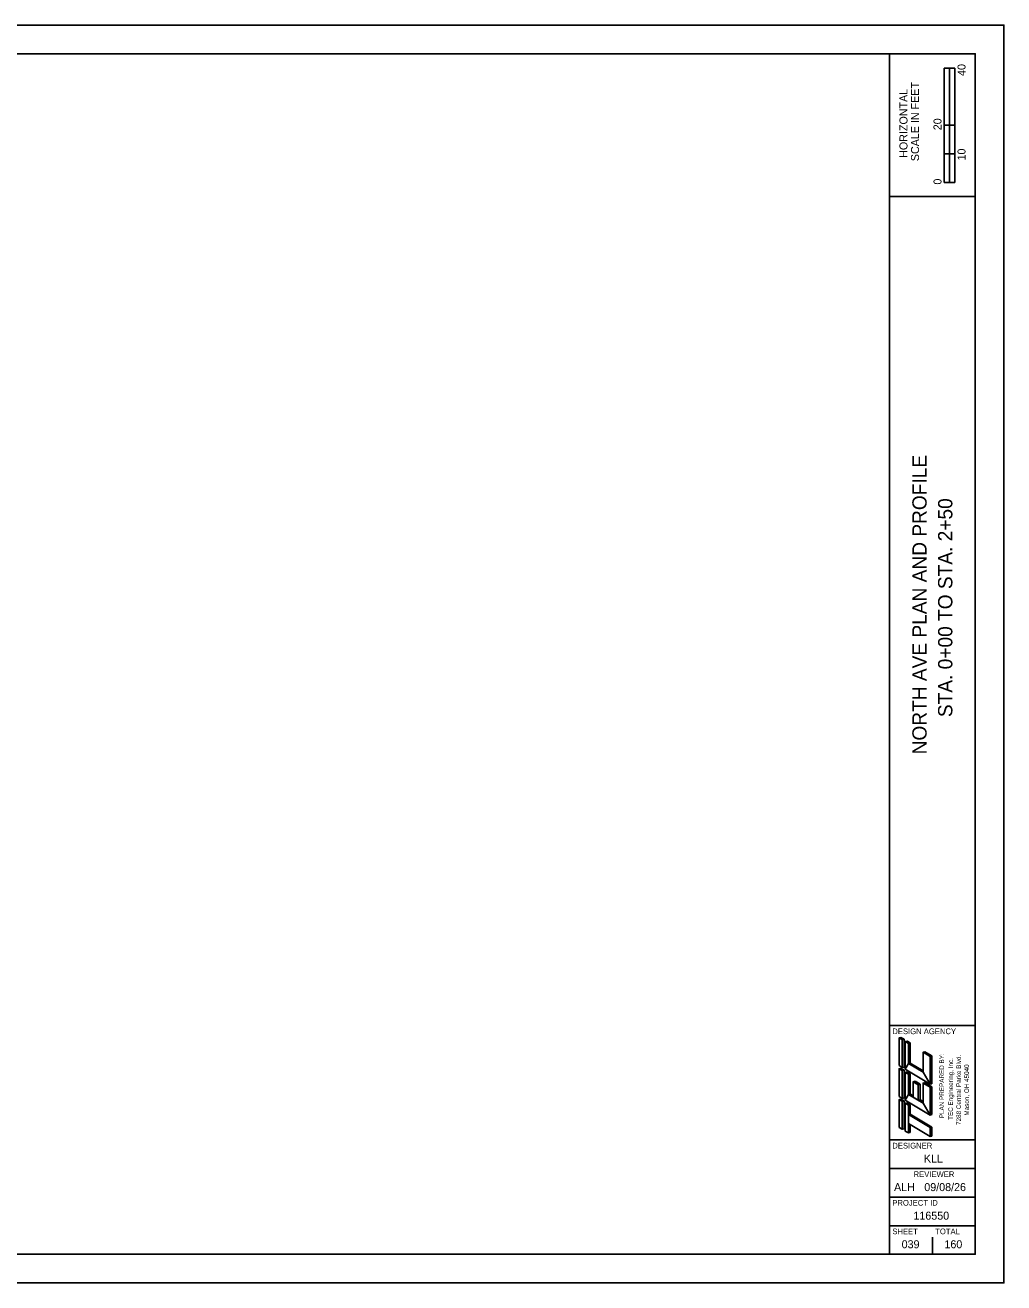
# Model space of a CAD drawing. Extents: x -0.2 to 34, y 0 to 22.
# Drawn here: x 16.89 to 34, y 0 to 22 of the extents above; entities that cross this region are included whole.
import ezdxf

# ---------------------------------------------------------------- set-up
doc = ezdxf.new("R2010")
doc.units = 0
for name, color, linetype in [('Default', 7, 'Continuous'), ('DT_X_Contour_Major', 7, 'Continuous'), ('DT_X_Contour_Minor', 7, 'Continuous'), ('DT_X_Spot_Elev', 7, 'Continuous'), ('DT_X_Void', 7, 'Continuous')]:
    doc.layers.add(name, color=color, linetype=linetype)

msp = doc.modelspace()

# ---------------------------------------------------------------- linework, layer by layer
at = {"layer": 'DT_X_Contour_Major'}
for p, q in [((32, 0.5), (32, 21.5)), ((32, 19), (33.5, 19)), ((32, 4.5), (33.5, 4.5)), ((32, 2.5), (33.5, 2.5)), ((32, 2), (33.5, 2)), ((32, 1.5), (33.5, 1.5)), ((32, 1), (33.5, 1))]:
    msp.add_line(p, q, dxfattribs=at)
msp.add_lwpolyline([(1.5, 21.5), (33.5, 21.5), (33.5, 0.5), (1.5, 0.5)], close=True, dxfattribs=at)
at = {"layer": 'DT_X_Contour_Minor'}
msp.add_lwpolyline([(0, 0), (34, 0), (34, 22), (0, 22)], close=True, dxfattribs=at)
at = {"layer": 'DT_X_Spot_Elev'}
for p, q in [((32.957, 19.25), (32.957, 21.25)), ((33.144, 21.25), (32.957, 21.25)), ((32.957, 20.25), (32.957, 21.25)), ((32.957, 21.25), (33.05, 21.25)), ((33.05, 21.25), (33.051, 21.25)), ((33.051, 21.25), (33.051, 20.25)), ((33.144, 21.25), (33.144, 19.25)), ((33.051, 20.25), (32.957, 20.25)), ((33.143, 20.25), (33.05, 20.25)), ((33.05, 20.25), (33.05, 19.75)), ((33.143, 19.75), (33.143, 20.25)), ((33.05, 19.75), (32.957, 19.75)), ((32.957, 19.75), (32.957, 19.25)), ((33.05, 19.25), (33.05, 19.75)), ((33.05, 19.75), (33.143, 19.75)), ((33.144, 19.25), (32.957, 19.25)), ((32.957, 19.25), (33.05, 19.25)), ((32.75, 3.5), (32.75, 3.5)), ((32.375, 0.675), (32.375, 0.675)), ((32.75, 0.5), (32.75, 0.8))]:
    msp.add_line(p, q, dxfattribs=at)
at = {"layer": 'DT_X_Void'}
for p, q in [((32.169, 4.285), (32.201, 4.294)), ((32.169, 3.799), (32.169, 4.285)), ((32.223, 4.253), (32.169, 4.285)), ((32.255, 4.261), (32.201, 4.294)), ((32.223, 4.253), (32.255, 4.261)), ((32.223, 3.767), (32.223, 4.253)), ((32.255, 3.775), (32.255, 4.261)), ((32.277, 4.221), (32.309, 4.229)), ((32.331, 4.188), (32.277, 4.221)), ((32.277, 3.735), (32.277, 4.221)), ((32.309, 4.229), (32.363, 4.196)), ((32.331, 4.188), (32.363, 4.196)), ((32.331, 3.837), (32.331, 4.188)), ((32.363, 4.196), (32.363, 3.845)), ((32.587, 4.034), (32.62, 4.042)), ((32.587, 3.683), (32.587, 4.034)), ((32.709, 3.961), (32.587, 4.034)), ((32.62, 4.042), (32.741, 3.97)), ((32.709, 3.961), (32.741, 3.97)), ((32.709, 3.475), (32.709, 3.961)), ((32.741, 3.97), (32.741, 3.484)), ((32.223, 3.767), (32.169, 3.799)), ((32.169, 3.745), (32.201, 3.754)), ((32.169, 3.259), (32.169, 3.745)), ((32.223, 3.713), (32.169, 3.745)), ((32.255, 3.722), (32.201, 3.754)), ((32.223, 3.767), (32.255, 3.775)), ((32.331, 3.837), (32.363, 3.845)), ((32.587, 3.683), (32.331, 3.837)), ((32.363, 3.845), (32.587, 3.711)), ((32.223, 3.713), (32.255, 3.722)), ((32.223, 3.227), (32.223, 3.713)), ((32.255, 3.236), (32.255, 3.722)), ((32.709, 3.475), (32.277, 3.735)), ((32.277, 3.681), (32.309, 3.689)), ((32.277, 3.195), (32.277, 3.681)), ((32.331, 3.648), (32.277, 3.681)), ((32.309, 3.689), (32.363, 3.656)), ((32.331, 3.648), (32.363, 3.656)), ((32.331, 3.297), (32.331, 3.648)), ((32.363, 3.656), (32.363, 3.305)), ((32.415, 3.519), (32.448, 3.527)), ((32.448, 3.527), (32.535, 3.474)), ((32.331, 3.297), (32.363, 3.305)), ((32.363, 3.305), (32.415, 3.274)), ((32.415, 3.519), (32.415, 3.247)), ((32.415, 3.519), (32.503, 3.466)), ((32.503, 3.466), (32.535, 3.474)), ((32.503, 3.466), (32.503, 3.194)), ((32.535, 3.474), (32.535, 3.202)), ((32.587, 3.494), (32.62, 3.502)), ((32.587, 3.143), (32.587, 3.494)), ((32.709, 3.421), (32.587, 3.494)), ((32.62, 3.502), (32.741, 3.43)), ((32.709, 3.475), (32.741, 3.484)), ((32.709, 3.421), (32.741, 3.43)), ((32.709, 2.935), (32.709, 3.421)), ((32.741, 3.43), (32.741, 2.944)), ((32.223, 3.227), (32.169, 3.259)), ((32.169, 3.205), (32.201, 3.215)), ((32.169, 2.719), (32.169, 3.205)), ((32.223, 3.173), (32.169, 3.205)), ((32.255, 3.181), (32.201, 3.215)), ((32.222, 3.173), (32.255, 3.181)), ((32.223, 3.227), (32.255, 3.236)), ((32.223, 2.687), (32.223, 3.173)), ((32.255, 2.695), (32.255, 3.181)), ((32.709, 2.935), (32.277, 3.195)), ((32.277, 3.141), (32.309, 3.151)), ((32.331, 3.108), (32.277, 3.141)), ((32.277, 2.655), (32.277, 3.141)), ((32.309, 3.151), (32.363, 3.116)), ((32.415, 3.247), (32.331, 3.297)), ((32.331, 3.108), (32.363, 3.116)), ((32.331, 2.944), (32.331, 3.108)), ((32.363, 3.116), (32.363, 2.952)), ((32.503, 3.194), (32.535, 3.202)), ((32.587, 3.143), (32.503, 3.194)), ((32.535, 3.202), (32.587, 3.171)), ((32.331, 2.944), (32.363, 2.952)), ((32.331, 2.944), (32.709, 2.717)), ((32.363, 2.952), (32.741, 2.725)), ((32.709, 2.935), (32.741, 2.944)), ((32.223, 2.687), (32.169, 2.719)), ((32.223, 2.687), (32.255, 2.695)), ((32.331, 2.622), (32.277, 2.655)), ((32.331, 2.787), (32.709, 2.56)), ((32.331, 2.622), (32.331, 2.787)), ((32.363, 2.63), (32.363, 2.767)), ((32.709, 2.717), (32.741, 2.725)), ((32.709, 2.56), (32.709, 2.717)), ((32.741, 2.725), (32.741, 2.568)), ((32.331, 2.622), (32.363, 2.63)), ((32.709, 2.56), (32.741, 2.568))]:
    msp.add_line(p, q, dxfattribs=at)
for points in [[(32.169, 3.799), (32.223, 3.767), (32.223, 4.253), (32.169, 4.285)], [(32.277, 3.735), (32.331, 3.837), (32.331, 4.188), (32.277, 4.221)], [(32.709, 3.475), (32.587, 3.683), (32.587, 4.034), (32.709, 3.961)], [(32.169, 3.259), (32.223, 3.227), (32.223, 3.713), (32.169, 3.745)], [(32.277, 3.735), (32.331, 3.837), (32.587, 3.683), (32.709, 3.475)], [(32.277, 3.195), (32.331, 3.297), (32.331, 3.648), (32.277, 3.681)], [(32.415, 3.247), (32.415, 3.519), (32.503, 3.466), (32.503, 3.194)], [(32.709, 2.935), (32.587, 3.143), (32.587, 3.494), (32.709, 3.421)], [(32.169, 2.719), (32.223, 2.687), (32.223, 3.173), (32.169, 3.205)], [(32.277, 3.195), (32.331, 3.297), (32.587, 3.143), (32.709, 2.935)], [(32.277, 2.655), (32.331, 2.622), (32.331, 3.108), (32.277, 3.141)], [(32.331, 2.787), (32.331, 2.944), (32.709, 2.717), (32.709, 2.56)]]:
    msp.add_lwpolyline(points, close=True, dxfattribs=at)

# ---------------------------------------------------------------- texts
at = {"layer": 'Default'}
for s, p in [('PLAN PREPARED BY:', (32.954, 2.88)), ('TEC Engineering, Inc.', (33.11, 2.851)), ('7288 Central Parke Blvd.', (33.25, 2.762)), ('Mason, OH 45040', (33.39, 2.925))]:
    msp.add_text(s, height=0.08, rotation=90, dxfattribs=at).set_placement(p)
at = {"layer": 'DT_X_Spot_Elev'}
for s, height, p in [('40', 0.14, (33.33, 21.112)), ('SCALE IN FEET', 0.14, (32.517, 19.621)), ('HORIZONTAL', 0.14, (32.315, 19.679)), ('20', 0.14, (32.91, 20.162)), ('10', 0.14, (33.33, 19.633)), ('0', 0.14, (32.91, 19.211)), ('NORTH AVE PLAN AND PROFILE', 0.25, (32.65, 9.244)), ('STA. 0+00 TO STA. 2+50', 0.25, (33.1, 9.896))]:
    msp.add_text(s, height=height, rotation=90, dxfattribs=at).set_placement(p)
for s, height, p in [('DESIGN AGENCY', 0.1, (32.05, 4.35)), ('DESIGNER', 0.1, (32.05, 2.35)), ('KLL', 0.14, (32.601, 2.105)), ('REVIEWER', 0.1, (32.422, 1.85)), ('ALH', 0.14, (32.08, 1.605)), ('09/08/26', 0.14, (32.609, 1.605)), ('PROJECT ID', 0.1, (32.05, 1.35)), ('116550', 0.14, (32.419, 1.105)), ('SHEET', 0.1, (32.05, 0.85)), ('TOTAL', 0.1, (32.8, 0.85)), ('039', 0.14, (32.213, 0.605)), ('160', 0.14, (32.961, 0.605))]:
    msp.add_text(s, height=height, dxfattribs=at).set_placement(p)

doc.saveas('drawing.dxf')
